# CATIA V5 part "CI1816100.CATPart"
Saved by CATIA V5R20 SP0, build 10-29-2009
Part number: CI1816100
Bounding box of the stored display mesh (mm): x -15 to 15, y -11.308 to 124, z -19.756 to 16.81
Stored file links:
  C:\Users\Raffaele\Desktop\3D X SITO CF\BOLEX\19-INCLINED ASSEMBLY REF_CI\CI1816100.CATPart

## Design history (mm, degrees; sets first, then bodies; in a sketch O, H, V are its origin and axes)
Set1
  DatumSurface1 to DatumSurface16 "MANIFOLD_SOLID_BREP #385"
  DatumSurface17 to DatumSurface39 "MANIFOLD_SOLID_BREP #1110"
Body1 (main body)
